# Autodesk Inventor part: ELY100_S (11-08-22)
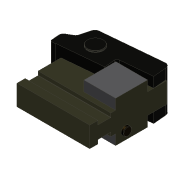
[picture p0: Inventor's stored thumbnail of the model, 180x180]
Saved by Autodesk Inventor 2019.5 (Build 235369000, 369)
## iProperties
Created: 2022-08
Part Number: ELY100_S (11-08-22)
Material: St37-2 / S235
Document SubType Name: Modeling
Designer: schoth
Density: 7.86 g/cm^3
Appearance: Steel
RuleStatus: InUse
Author: schoth
Mass(KG): 0.0
Area(mm): 0.0
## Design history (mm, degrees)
derived "ELY100.iam"
body "Solid1"
node "FB205-005.ipt:1"
node "ELY100-88.iam:1::FB209-030.ipt:1"
node "ELY100-88.iam:1::CS235-006.ipt:1"
node "ELY100-99.iam:1::FB206-011.ipt:1"
node "ELY100-99.iam:1::FB207-104.ipt:1"
node "ELY100.iam_Bodies"
